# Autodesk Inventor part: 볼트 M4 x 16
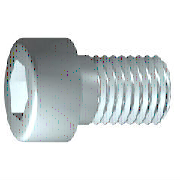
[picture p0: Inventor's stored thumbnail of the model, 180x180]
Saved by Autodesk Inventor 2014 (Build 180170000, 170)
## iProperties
IsCustomPart: 1
Created: 2012-02
Part Number: 볼트 M4 x 16
Material: 스테인리스강
Description: 6각 소켓 머리 캡 나사
Document SubType Name: Modeling
Standard: ISO 4762
Designer: mduedu
Standard Revision: Fourth edition 2004-03-01
Standards Organization: ISO
Language: ko-KR
Size Designation: M4 x 16
Categories: <MemberInstance><Categories><Category DisplayName="조임쇠" InternalName="e4da775c-781d-43d5-af7c-5136215cf5a6" Mnemonic="FSTN"><Category DisplayName="볼트" InternalN
Density: 8.08 g/cm^3
Mass: 2.70334 g
Surface Area: 3.81118 cm^2
Volume: 0.334572 cm^3
Appearance: 반광택
Author: mduedu
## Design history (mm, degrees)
sketch "스케치1"
  geometry: L1 (-1, 0)-(16, 0); L2 (16, 0)-(16, 2); L3 (16, 2)-(1.75, 2); L4 (1.75, 2)-(1.32, 2); L5 (1.32, 2)-(0, 2); L6 (0, 2)-(0, 3.5); L7 (0, 3.5)-(-4, 3.5); L8 (-4, 3.5)-(-4, 1.732); L9 (-4, 1.732)-(-2, 1.732); L10 (-2, 1.732)-(-1, 0); L11 (-8, 0)-(20, 0) reference; L12 (0, -0.7)-(0, 4.2) reference; L13 (1.75, 2)-(0, 2)
  constraints: 22 end point, 6 parallel, 2 collinear, 2 perpendicular, 1 horizontal, 1 point on line
  dimensions: "d1" = 14.25 distance from line of L3.end L2 (= GEL); "d2" = 0.42952 distance of L4.end L3.end (computed from GAL); "d3" = 4 distance between parallel lines of L8 L6 (= KOH); "d4" = 2 distance of L8.end L9.end (= INTI); "d5" = 60 deg angle of L10 L1; "d6" = 4 diameter of L3 L1 (= GD); "d7" = 4 diameter of L5 L1 (= BDM); "d8" = 3.4641 diameter of L9 L1 (= 1.1547 x SW); "d9" = 7 diameter of L7 L1 (= KOD); "d26" = 16 distance between parallel lines of L12 L2 (= NLG)
revolve "본체" sketch "스케치1" stored, may be unused: angle "d10" = 90 deg
sketch "스케치2"
  geometry: L1 (0, -4.9)-(0, 4.9) reference; L2 (-4.9, 0)-(4.9, 0) reference; L3 (1.732, 0)-(0.866, -1.5); L4 (0.866, -1.5)-(-0.866, -1.5); L5 (-0.866, -1.5)-(-1.732, 0); L6 (-1.732, 0)-(-0.866, 1.5); L7 (-0.866, 1.5)-(0.866, 1.5); L8 (0.866, 1.5)-(1.732, 0); 2 further points
  constraints: 12 end point, 1 coincident, 1 horizontal alignment, 1 point on line, 12 other
extrude "슬롯" join sketch "스케치2" stored distance "d11" = 10; taper "d12" = 0 deg
workplane "Work Plane1"
fillet "Fillet2" dims "d30" = 0.1 (= R)
body "Solid1"
fillet "모깎기1" dims "d17" = 0.4 (= RR)
feature "스레드" dims "d13" = 14.25 (= GEL), "d14" = 0
chamfer "모따기1" distance "d15" = 0.42941 (= -0.5 x SPD + 0.5 x GD); stored, may be unused: second distance "d16" = 0.42941 (= GUL), angle "d27" = 45 deg
other parameters: "GD" = 4 [user parameter; used in 2 equation terms], "NLG" = 16 [user parameter; used in 1 equation term], "GEL" = 14.25 [user parameter; used in 2 equation terms], "KOD" = 7 [user parameter; used in 1 equation term], "KOH" = 4 [user parameter; used in 1 equation term], "INTI" = 2 [user parameter; used in 1 equation term], "GAL" = 0.42941 (= 0.61345 x PTC) [user parameter; used in 1 equation term], "GUL" = 0.42941 (= 0.61345 x PTC) [user parameter; used in 1 equation term], "BDM" = 4 (= NND) [user parameter; used in 1 equation term], "SW" = 3 [user parameter; used in 2 equation terms], "RR" = 0.4 [user parameter; used in 1 equation term], "SPD" = 3.14117 (= NND - 1.2269 x PTC) [user parameter; used in 1 equation term], "d19" = 0, "d28" = 0, "d29" = 0, "R" = 0.1 [user parameter; used in 1 equation term], "TOA" = 30 deg [user parameter], "GD1" = 3.14117 (= THREADDIA - 1.2269 x PTC) [user parameter], "THREADDIA" = 4 [user parameter; used in 1 equation term], "FAWI" = 45 deg [user parameter], "TPU" = 14.28571 (computed from PTC) [user parameter], "PTC" = 0.7 [user parameter; used in 5 equation terms], "NND" = 4 [user parameter; used in 2 equation terms], "E0" = 3.465 (= 1.155 x SW) [user parameter]
